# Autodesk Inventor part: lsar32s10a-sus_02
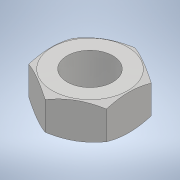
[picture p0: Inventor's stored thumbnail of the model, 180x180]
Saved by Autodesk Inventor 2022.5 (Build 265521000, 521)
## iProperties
Part Number: lsar32s10a-sus_02
Material: 一般
Document SubType Name: Modeling
Designer: ImaoCorp
Density: 1 g/cm^3
Appearance: 既定
Author: ImaoCorp
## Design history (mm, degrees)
feature "lsar32s10a-sus_02"
node "ソリッド1"
